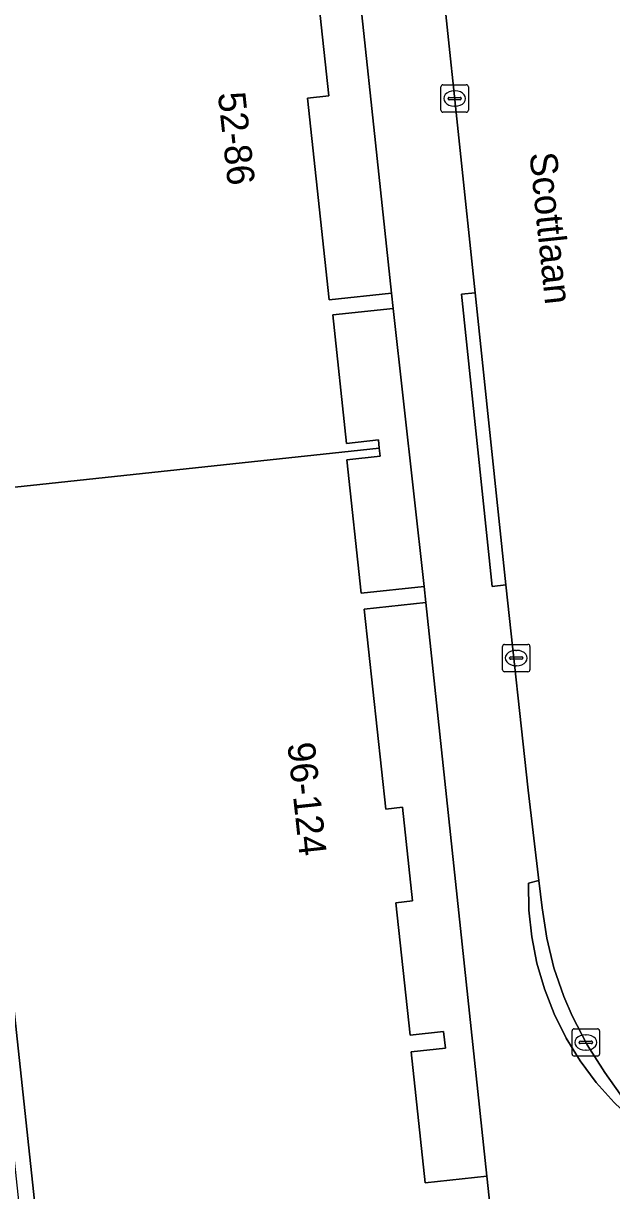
# Model space of a CAD drawing. Extents: x 161248 to 161848, y 384871 to 385383.
# Drawn here: x 161334.46 to 161355.95, y 384949.31 to 384991.92 of the extents above; entities that cross this region are included whole.
import ezdxf

# ---------------------------------------------------------------- set-up
doc = ezdxf.new("R2010")
doc.units = 0
for name, color, linetype in [('IMGEO_Kolk', 7, 'Continuous'), ('IMGEO_Openbare_ruimte_label', 7, 'Continuous'), ('IMGEO_Pand', 7, 'Continuous'), ('IMGEO_Pand_nummerreeks', 7, 'Continuous'), ('IMGEO_Rijbaan_lokaal_open', 7, 'Continuous'), ('IMGEO_Voetpad_open', 7, 'Continuous')]:
    doc.layers.add(name, color=color, linetype=linetype)

msp = doc.modelspace()

# ---------------------------------------------------------------- linework, layer by layer
at = {"layer": 'IMGEO_Kolk'}
for p, q in [((161349.718, 384988.745), (161349.718, 384989.597)), ((161349.793, 384989.671), (161350.645, 384989.671)), ((161350.206, 384989.451), (161350.231, 384989.451)), ((161350.719, 384989.597), (161350.719, 384988.745)), ((161349.977, 384989.165), (161349.977, 384989.177)), ((161350.415, 384989.128), (161350.017, 384989.128)), ((161350.02, 384989.214), (161350.418, 384989.214)), ((161350.229, 384988.891), (161350.204, 384988.891)), ((161350.461, 384989.177), (161350.461, 384989.165)), ((161350.645, 384988.671), (161349.793, 384988.671)), ((161351.968, 384968.323), (161351.968, 384969.175)), ((161352.043, 384969.249), (161352.895, 384969.249)), ((161352.456, 384969.029), (161352.481, 384969.029)), ((161352.969, 384969.175), (161352.969, 384968.323)), ((161352.227, 384968.743), (161352.227, 384968.755)), ((161352.665, 384968.706), (161352.267, 384968.706)), ((161352.27, 384968.792), (161352.668, 384968.792)), ((161352.479, 384968.469), (161352.454, 384968.469)), ((161352.711, 384968.755), (161352.711, 384968.743)), ((161352.895, 384968.249), (161352.043, 384968.249)), ((161354.585, 384955.219), (161355.437, 384955.219)), ((161354.51, 384954.293), (161354.51, 384955.145)), ((161354.998, 384954.999), (161355.023, 384954.999)), ((161355.511, 384955.145), (161355.511, 384954.293)), ((161354.769, 384954.713), (161354.769, 384954.725)), ((161355.207, 384954.676), (161354.809, 384954.676)), ((161354.812, 384954.762), (161355.21, 384954.762)), ((161355.021, 384954.439), (161354.996, 384954.439)), ((161355.253, 384954.725), (161355.253, 384954.713)), ((161355.437, 384954.219), (161354.585, 384954.219))]:
    msp.add_line(p, q, dxfattribs=at)
for points in [[(161349.718, 384988.745), (161349.718, 384989.597)], [(161349.793, 384989.671), (161350.645, 384989.671)], [(161350.719, 384989.597), (161350.719, 384988.745)], [(161350.645, 384988.671), (161349.793, 384988.671)], [(161351.968, 384968.323), (161351.968, 384969.175)], [(161352.043, 384969.249), (161352.895, 384969.249)], [(161352.969, 384969.175), (161352.969, 384968.323)], [(161352.895, 384968.249), (161352.043, 384968.249)], [(161354.585, 384955.219), (161355.437, 384955.219)], [(161354.51, 384954.293), (161354.51, 384955.145)], [(161355.511, 384955.145), (161355.511, 384954.293)], [(161355.437, 384954.219), (161354.585, 384954.219)]]:
    msp.add_lwpolyline(points, dxfattribs=at)
for centre, radius, start, end in [((161349.795, 384989.595), 0.0765, 91.552, 178.448), ((161349.795, 384989.595), 0.0765, 91.552, 178.448), ((161350.643, 384989.595), 0.0765, 1.552, 88.448), ((161350.643, 384989.595), 0.0765, 1.552, 88.448), ((161350.017, 384989.174), 0.0403, 85.8775, 175.7526), ((161350.014, 384989.164), 0.0366, 178.938, 274.7102), ((161350.418, 384989.171), 0.043, 264.8664, 352.4533), ((161350.422, 384989.176), 0.0386, 1.7309, 96.639), ((161349.795, 384988.747), 0.0765, 181.552, 268.448), ((161349.795, 384988.747), 0.0765, 181.552, 268.448), ((161350.643, 384988.747), 0.0765, 271.552, 358.448), ((161350.643, 384988.747), 0.0765, 271.552, 358.448), ((161352.045, 384969.173), 0.0765, 91.552, 178.448), ((161352.045, 384969.173), 0.0765, 91.552, 178.448), ((161352.893, 384969.173), 0.0765, 1.552, 88.448), ((161352.893, 384969.173), 0.0765, 1.552, 88.448), ((161352.267, 384968.752), 0.0403, 85.8775, 175.7526), ((161352.264, 384968.742), 0.0366, 178.938, 274.7102), ((161352.668, 384968.749), 0.043, 264.8664, 352.4533), ((161352.672, 384968.754), 0.0386, 1.7309, 96.639), ((161352.045, 384968.325), 0.0765, 181.552, 268.448), ((161352.045, 384968.325), 0.0765, 181.552, 268.448), ((161352.893, 384968.325), 0.0765, 271.552, 358.448), ((161352.893, 384968.325), 0.0765, 271.552, 358.448), ((161354.587, 384955.143), 0.0765, 91.552, 178.448), ((161354.587, 384955.143), 0.0765, 91.552, 178.448), ((161355.435, 384955.143), 0.0765, 1.552, 88.448), ((161355.435, 384955.143), 0.0765, 1.552, 88.448), ((161354.809, 384954.722), 0.0403, 85.8775, 175.7526), ((161354.806, 384954.712), 0.0366, 178.938, 274.7102), ((161355.21, 384954.719), 0.043, 264.8664, 352.4533), ((161355.214, 384954.724), 0.0386, 1.7309, 96.639), ((161354.587, 384954.295), 0.0765, 181.552, 268.448), ((161354.587, 384954.295), 0.0765, 181.552, 268.448), ((161355.435, 384954.295), 0.0765, 271.552, 358.448), ((161355.435, 384954.295), 0.0765, 271.552, 358.448)]:
    msp.add_arc(centre, radius, start, end, dxfattribs=at)
for centre, major_axis, ratio, start_param, end_param in [((161350.205, 384989.171), (-0.387, 0.002), 0.722429, 4.712389, 7.853982), ((161350.23, 384989.171), (-0.39, 0.002), 0.717154, 1.570796, 4.712389), ((161352.455, 384968.749), (-0.387, 0.002), 0.722429, 4.712389, 7.853982), ((161352.48, 384968.749), (-0.39, 0.002), 0.717154, 1.570796, 4.712389), ((161354.997, 384954.719), (-0.387, 0.002), 0.722429, 4.712389, 7.853982), ((161355.022, 384954.719), (-0.39, 0.002), 0.717154, 1.570796, 4.712389)]:
    msp.add_ellipse(centre, major_axis=major_axis, ratio=ratio, start_param=start_param, end_param=end_param, dxfattribs=at)
at = {"layer": 'IMGEO_Pand'}
for points in [[(161345.639, 384981.819), (161344.847, 384989.184), (161345.626, 384989.268), (161345.261, 384992.657), (161344.504, 384992.575), (161343.986, 384997.395), (161345.22, 384997.527), (161345.188, 384997.822), (161329.788, 384996.166), (161332.09, 384974.761), (161347.464, 384976.414), (161347.432, 384976.709), (161346.267, 384976.583), (161345.763, 384981.275), (161347.976, 384981.513), (161347.916, 384982.064)], [(161349.099, 384971.364), (161346.806, 384971.118), (161346.282, 384975.989), (161347.495, 384976.119), (161347.464, 384976.414), (161332.09, 384974.761), (161335.907, 384939.267), (161352.34, 384941.034), (161351.394, 384949.836), (161349.145, 384949.594), (161348.631, 384954.373), (161349.881, 384954.507), (161349.815, 384955.119), (161348.591, 384954.987), (161348.072, 384959.82), (161348.677, 384959.885), (161348.309, 384963.303), (161347.699, 384963.238), (161346.913, 384970.539), (161349.162, 384970.781)]]:
    msp.add_lwpolyline(points, close=True, dxfattribs=at)
at = {"layer": 'IMGEO_Rijbaan_lokaal_open'}
msp.add_lwpolyline([(161346.251, 385026.361), (161346.412, 385024.863), (161347.622, 385013.594), (161348.704, 385003.522), (161349.082, 385000), (161349.418, 384996.821), (161349.825, 384992.946), (161350.964, 384982.082), (161352.083, 384971.42), (161352.903, 384963.923), (161353.293, 384960.634), (161353.412, 384959.629), (161353.581, 384958.529), (161353.847, 384957.448), (161354.209, 384956.395), (161354.511, 384955.694), (161355.059, 384954.63), (161355.7, 384953.619), (161356.682, 384952.243)], dxfattribs=at)
at = {"layer": 'IMGEO_Voetpad_open'}
for points in [[(161343.203, 385026.481), (161343.3, 385025.559), (161343.862, 385025.619), (161345.069, 385014.386), (161345.626, 385014.446), (161346.272, 385008.441), (161345.12, 385008.375), (161345.635, 385003.548), (161346.825, 384992.221), (161347.327, 384987.554), (161347.916, 384982.064), (161347.976, 384981.513), (161349.099, 384971.364), (161349.162, 384970.781), (161351.394, 384949.836), (161352.34, 384941.034), (161352.588, 384941.054), (161354.608, 384941.218)], [(161352.083, 384971.42), (161351.587, 384971.365), (161350.468, 384982.027), (161350.964, 384982.082), (161349.825, 384992.946), (161349.328, 384992.891), (161348.579, 385000), (161348.214, 385003.468), (161348.704, 385003.522), (161347.622, 385013.594), (161347.145, 385013.539), (161345.918, 385024.806), (161346.412, 385024.863), (161346.251, 385026.361)], [(161333.36, 384957.504), (161335.385, 384938.672), (161352.645, 384940.528), (161352.588, 384941.054), (161352.34, 384941.034), (161335.907, 384939.267), (161332.09, 384974.761)], [(161357.714, 384950.796), (161357.446, 384951.172), (161356.682, 384952.243), (161356.523, 384952.075), (161356.048, 384952.531), (161355.394, 384953.261), (161354.808, 384954.047), (161354.294, 384954.881), (161353.856, 384955.759), (161353.499, 384956.672), (161353.225, 384957.613), (161353.036, 384958.575), (161352.934, 384959.55), (161352.919, 384960.53), (161353.293, 384960.634), (161352.903, 384963.923), (161352.083, 384971.42)]]:
    msp.add_lwpolyline(points, dxfattribs=at)
for points in [[(161346.825, 384992.221), (161345.635, 385003.548), (161345.12, 385008.375), (161344.547, 385013.744), (161342.326, 385013.505), (161343.119, 385006.139), (161343.632, 385006.194), (161343.994, 385002.836), (161343.407, 385002.773), (161343.705, 385000), (161343.922, 384997.985), (161345.156, 384998.117), (161345.188, 384997.822), (161345.22, 384997.527), (161343.986, 384997.395), (161344.504, 384992.575), (161345.261, 384992.657), (161345.626, 384989.268), (161344.847, 384989.184), (161345.639, 384981.819), (161347.916, 384982.064), (161347.327, 384987.554)], [(161350.964, 384982.082), (161350.468, 384982.027), (161351.587, 384971.365), (161352.083, 384971.42)], [(161347.976, 384981.513), (161345.763, 384981.275), (161346.267, 384976.583), (161347.432, 384976.709), (161347.464, 384976.414), (161347.495, 384976.119), (161346.282, 384975.989), (161346.806, 384971.118), (161349.099, 384971.364)], [(161349.162, 384970.781), (161346.913, 384970.539), (161347.699, 384963.238), (161348.309, 384963.303), (161348.677, 384959.885), (161348.072, 384959.82), (161348.591, 384954.987), (161349.815, 384955.119), (161349.881, 384954.507), (161348.631, 384954.373), (161349.145, 384949.594), (161351.394, 384949.836)], [(161355.059, 384954.63), (161354.511, 384955.694), (161354.209, 384956.395), (161353.847, 384957.448), (161353.581, 384958.529), (161353.412, 384959.629), (161353.293, 384960.634), (161352.919, 384960.53), (161352.934, 384959.55), (161353.036, 384958.575), (161353.225, 384957.613), (161353.499, 384956.672), (161353.856, 384955.759), (161354.294, 384954.881), (161354.808, 384954.047), (161355.394, 384953.261), (161356.048, 384952.531), (161356.523, 384952.075), (161356.682, 384952.243), (161355.7, 384953.619)]]:
    msp.add_lwpolyline(points, close=True, dxfattribs=at)

# ---------------------------------------------------------------- texts
at = {"layer": 'IMGEO_Openbare_ruimte_label'}
msp.add_text('Scottlaan', height=1, rotation=275.967, dxfattribs=at).set_placement((161352.949, 384987.167))
at = {"layer": 'IMGEO_Pand_nummerreeks'}
for s, rotation, p in [('52-86', 276.2547, (161341.567, 384989.361)), ('96-124', 276.1905, (161344.107, 384965.625))]:
    msp.add_text(s, height=1, rotation=rotation, dxfattribs=at).set_placement(p)

doc.saveas('drawing.dxf')
